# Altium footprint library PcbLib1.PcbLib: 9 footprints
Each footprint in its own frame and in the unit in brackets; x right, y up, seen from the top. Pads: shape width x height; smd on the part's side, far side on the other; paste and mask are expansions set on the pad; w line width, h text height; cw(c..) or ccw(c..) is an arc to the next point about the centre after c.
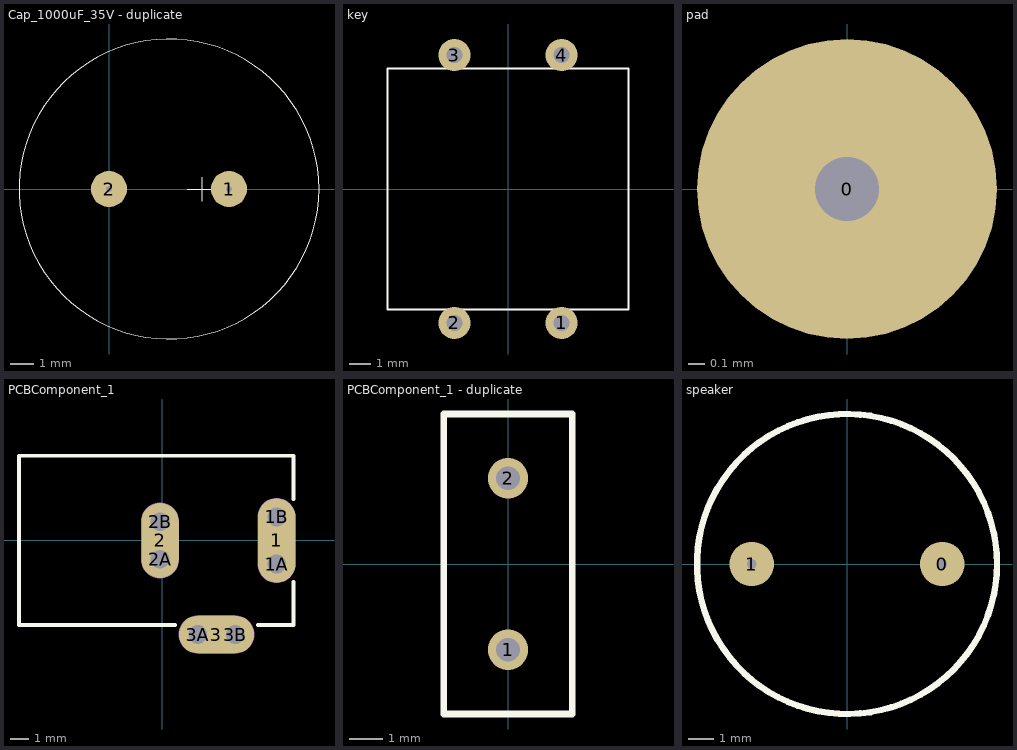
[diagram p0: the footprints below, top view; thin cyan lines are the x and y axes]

## Cap_1000uF_35V [mm]

## Cap_1000uF_35V - duplicate [mil]
pads (2):
  round 60 hole 10: 1(200,0) 2(0,0)
Top Overlay:
  circle w2: c100,0 r250
  lines w2: 130,0 170,0 ; 155,-20 155,20
3D body "cap35v1000uF.STEP": height 1000, standoff -150, extent -150,-250 350,250

## key [mil]
pads (4):
  round 60 hole 30: 1(100,-250) 2(-100,-250) 3(-100,250) 4(100,250)
Top Overlay:
  lines w3.94: -225,-225 -225,225 225,225 225,-225 -225,-225
3D body "key.STEP": height 470, standoff 0, extent -249.99,-250 250.01,250

## pad [mil]
pads (1):
  round 70 hole 15: 0(0,0)

## PCBComponent_1 [mm]
pads (9):
  oval 2x4.5 all layers, no hole: 1(6.08,0)
  round 1.5 hole 1: 1A(6.08,-1.25) 1B(6.08,1.25) 2A(-0.12,-1) 2B(-0.12,1) 3A(1.88,-5) 3B(3.88,-5)
  oval 2x4 all layers, no hole: 2(-0.12,0)
  oval 4x2 all layers, no hole: 3(2.88,-5)
Top Overlay:
  lines w0.2: 0.68,-4.5 -7.62,-4.5 -7.62,4.5 6.98,4.5 6.98,2.2 ; 5.08,-4.5 6.98,-4.5 6.98,-2.2
Mechanical 1:
  lines w1: -0.12,-1 -0.12,1 ; 1.88,-5 3.88,-5 ; 6.08,-1.25 6.08,1.25
  text "Mech 2 - Clearance, move to internal plane if present" at -7.334,5.066 h0.3
  text "Alert PCB fab to slot details" at -7.334,6.066 h0.3
  text "Mech 1 - Slot cut-out" at -7.334,5.566 h0.3
  text "Assign keep-out area to slot" at -7.334,6.566 h0.3
Mechanical 2:
  lines w2.016: -0.12,-1 -0.12,1 ; 1.88,-5 3.88,-5 ; 6.08,-1.25 6.08,1.25
3D body "User Library-dc50-1.step": height 11, standoff -1.2, extent -7.874,-5.6 6.826,5.6

## PCBComponent_1 - duplicate [mm]
pads (2):
  round 1.2 hole 0.7: 1(0,-2.54) 2(0,2.54)
Top Overlay:
  lines w0.2: -1.905,-4.445 1.905,-4.445 1.905,4.445 -1.905,4.445 -1.905,-4.445
3D body "User Library-HC-49_LT_THT_16MHz.STEP": height 3.6, standoff -1.99, extent -2.325,-5.675 2.325,5.675

## PCBComponent_1 - duplicate1 [mm]

## SO-8 [mm]

## speaker [mil]
pads (2):
  round 70 hole 15: 0(150,0) 1(-150,0)
Top Overlay:
  circle w10: c0,0 r236.22
3D body "speaker.STEP": height 374.02, standoff -118.11, extent -236.22,-236.22 236.22,236.22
